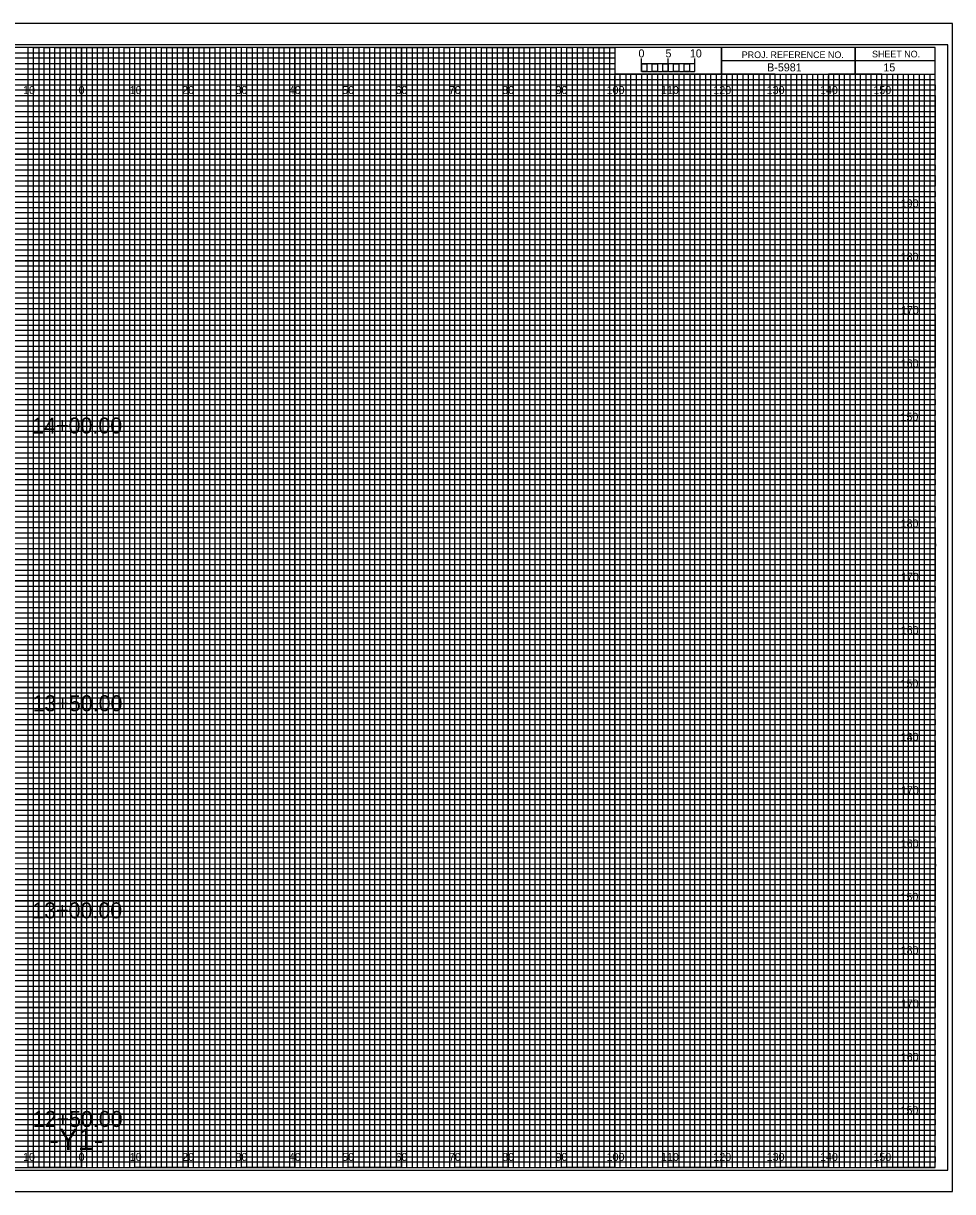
# Model space of a CAD drawing. Extents: x -13 to 323, y -5 to 434.
# Drawn here: x 149.1 to 323.3, y 215.5 to 434.5 of the extents above; entities that cross this region are included whole.
import ezdxf

# ---------------------------------------------------------------- set-up
doc = ezdxf.new("R2010")
doc.units = 0
for name, color, linetype in [('Exist Cross Section Cell', 7, 'Continuous'), ('Exist XS Center Line Elevation Label', 7, 'Continuous'), ('Exist XS Ground Line', 7, 'Continuous'), ('Prop CMT Concrete Structures', 7, 'Continuous'), ('Prop CMT Guardrail Graphics', 7, 'Continuous'), ('Prop CMT Pvmt Course 1', 7, 'Continuous'), ('Prop CMT Pvmt Course 2', 7, 'Continuous'), ('Prop CMT Pvmt Course 3', 7, 'Continuous'), ('Prop CMT Pvmt Surface', 7, 'Continuous'), ('Prop CMT Shld Paved Course 1', 7, 'Continuous'), ('Prop CMT Shld Paved Course 2', 7, 'Continuous'), ('Prop CMT Shld Paved Course 3', 7, 'Continuous'), ('Prop CMT Subgrade Earthwork', 7, 'Continuous'), ('Prop XS Ditch Standard Text', 7, 'Continuous'), ('Prop XS SE Text', 7, 'Continuous'), ('Prop XS Side Slope Text', 7, 'Continuous'), ('Scratch_Level_0', 7, 'Continuous')]:
    doc.layers.add(name, color=color, linetype=linetype)

msp = doc.modelspace()

# ---------------------------------------------------------------- linework, layer by layer
at = {"layer": 'Exist XS Center Line Elevation Label'}
for points in [[(145, 220), (155, 220), (155, 430), (165, 430), (165, 220), (175, 220), (175, 430), (185, 430), (185, 220), (195, 220), (195, 430), (205, 430), (205, 220), (215, 220), (215, 430), (225, 430), (225, 220), (235, 220), (235, 430), (245, 430), (245, 220), (255, 220), (255, 430), (259.93, 430), (260, 430), (260, 425), (264.99, 425), (264.99, 220), (275, 220), (275, 425), (285, 425), (285, 220), (295, 220), (295, 425), (305, 425), (305, 220), (315, 220), (315, 425)], [(0, 425), (275, 425)], [(0, 405), (320, 405), (320, 415), (0, 415)], [(0, 385), (320, 385), (320, 395), (0, 395)], [(0, 365), (320, 365), (320, 375), (0, 375)], [(0, 345), (320, 345), (320, 355), (0, 355)], [(0, 325), (320, 325), (320, 335), (0, 335)], [(0, 305), (320, 305), (320, 315), (0, 315)], [(0, 285), (320, 285), (320, 295), (0, 295)], [(0, 265), (320, 265), (320, 275), (0, 275)], [(0, 245), (320, 245), (320, 255), (0, 255)], [(0, 225), (320, 225), (320, 235), (0, 235)]]:
    msp.add_lwpolyline(points, dxfattribs=at)
at = {"layer": 'Exist XS Ground Line'}
for p, q in [((150, 430), (140, 430)), ((150, 220), (150, 430)), ((170, 430), (160, 430)), ((160, 430), (160, 220)), ((170, 220), (170, 430)), ((190, 430), (180, 430)), ((180, 430), (180, 220)), ((190, 220), (190, 430)), ((210, 430), (200, 430)), ((200, 430), (200, 220)), ((210, 220), (210, 430)), ((230, 430), (220, 430)), ((220, 430), (220, 220)), ((230, 220), (230, 430)), ((250, 430), (240, 430)), ((240, 430), (240, 220)), ((250, 220), (250, 430)), ((260, 430), (260, 220)), ((270, 220), (270, 425)), ((290, 425), (280, 425)), ((280, 425), (280, 220)), ((290, 220), (290, 425)), ((310, 425), (300, 425)), ((300, 425), (300, 220)), ((310, 220), (310, 425)), ((160, 220), (150, 220)), ((180, 220), (170, 220)), ((200, 220), (190, 220)), ((220, 220), (210, 220)), ((240, 220), (230, 220)), ((260, 220), (250, 220)), ((280, 220), (270, 220)), ((300, 220), (290, 220)), ((320, 220), (310, 220)), ((320, 220), (320, 220))]:
    msp.add_line(p, q, dxfattribs=at)
for points in [[(0, 420), (320, 420), (320, 410), (0, 410)], [(0, 400), (320, 400), (320, 390), (0, 390)], [(0, 380), (320, 380), (320, 370), (0, 370)], [(0, 360), (320, 360), (320, 350), (0, 350)], [(0, 340), (320, 340), (320, 330), (0, 330)], [(0, 320), (320, 320), (320, 310), (0, 310)], [(0, 300), (320, 300), (320, 290), (0, 290)], [(0, 280), (320, 280), (320, 270), (0, 270)], [(0, 260), (320, 260), (320, 250), (0, 250)], [(0, 240), (320, 240), (320, 230), (0, 230)]]:
    msp.add_lwpolyline(points, dxfattribs=at)
at = {"layer": 'Prop CMT Pvmt Course 1'}
for p, q in [((323.3, 434.5), (-13.4, 434.5)), ((-13.4, 215.5), (323.3, 215.5))]:
    msp.add_line(p, q, dxfattribs=at)
at = {"layer": 'Prop CMT Pvmt Course 2'}
msp.add_lwpolyline([(-13.4, 215.5), (323.3, 215.5), (323.3, 434.5), (-13.4, 434.5)], close=True, dxfattribs=at)
at = {"layer": 'Prop CMT Pvmt Course 3'}
msp.add_lwpolyline([(-10.8, 219.5), (322.4, 219.5), (322.4, 430.5), (-10.8, 430.5)], close=True, dxfattribs=at)
at = {"layer": 'Prop CMT Shld Paved Course 1'}
for p, q in [((305, 430), (305, 425)), ((305, 425), (305, 430)), ((280, 427.5), (280, 425)), ((320, 427.49), (280, 427.49)), ((280, 425), (320, 425))]:
    msp.add_line(p, q, dxfattribs=at)
for points in [[(320, 430), (0, 430), (0, 220), (320, 220)], [(280, 430), (260, 430), (260, 425.03), (280, 425.03)], [(320, 430), (280, 430), (280, 425), (320, 425)]]:
    msp.add_lwpolyline(points, close=True, dxfattribs=at)
at = {"layer": 'Prop CMT Shld Paved Course 2'}
for p, q in [((267, 425), (266.01, 425)), ((266.01, 425), (266.01, 220)), ((267, 220), (267, 425)), ((269, 425), (268, 425)), ((268, 425), (268, 220)), ((269, 220), (269, 425)), ((266.01, 220), (265, 220)), ((268, 220), (267, 220))]:
    msp.add_line(p, q, dxfattribs=at)
for points in [[(150, 220), (151, 220), (151, 430), (152, 430), (152, 220)], [(152, 220), (153, 220), (153, 430), (154, 430), (154, 220)], [(155, 220), (156, 220), (156, 430), (157, 430), (157, 220)], [(157, 220), (158, 220), (158, 430), (159, 430), (159, 220)], [(160, 220), (161, 220), (161, 430), (162, 430), (162, 220)], [(162, 220), (163, 220), (163, 430), (164, 430), (164, 220)], [(165, 220), (166, 220), (166, 430), (167, 430), (167, 220)], [(167, 220), (168, 220), (168, 430), (169, 430), (169, 220)], [(170, 220), (171, 220), (171, 430), (172, 430), (172, 220)], [(172, 220), (173, 220), (173, 430), (174, 430), (174, 220)], [(175, 220), (176, 220), (176, 430), (177, 430), (177, 220)], [(177, 220), (178, 220), (178, 430), (179, 430), (179, 220)], [(180, 220), (181, 220), (181, 430), (182, 430), (182, 220)], [(182, 220), (183, 220), (183, 430), (184, 430), (184, 220)], [(185, 220), (186, 220), (186, 430), (187, 430), (187, 220)], [(187, 220), (188, 220), (188, 430), (189, 430), (189, 220)], [(190, 220), (191, 220), (191, 430), (192, 430), (192, 220)], [(192, 220), (193, 220), (193, 430), (194, 430), (194, 220)], [(195, 220), (196, 220), (196, 430), (197, 430), (197, 220)], [(197, 220), (198, 220), (198, 430), (199, 430), (199, 220)], [(200, 220), (201, 220), (201, 430), (202, 430), (202, 220)], [(202, 220), (203, 220), (203, 430), (204, 430), (204, 220)], [(205, 220), (206, 220), (206, 430), (207, 430), (207, 220)], [(207, 220), (208, 220), (208, 430), (209, 430), (209, 220)], [(210, 220), (211, 220), (211, 430), (212, 430), (212, 220)], [(212, 220), (213, 220), (213, 430), (214, 430), (214, 220)], [(215, 220), (216, 220), (216, 430), (217, 430), (217, 220)], [(217, 220), (218, 220), (218, 430), (219, 430), (219, 220)], [(220, 220), (221, 220), (221, 430), (222, 430), (222, 220)], [(222, 220), (223, 220), (223, 430), (224, 430), (224, 220)], [(225, 220), (226, 220), (226, 430), (227, 430), (227, 220)], [(227, 220), (228, 220), (228, 430), (229, 430), (229, 220)], [(230, 220), (231, 220), (231, 430), (232, 430), (232, 220)], [(232, 220), (233, 220), (233, 430), (234, 430), (234, 220)], [(235, 220), (236, 220), (236, 430), (237, 430), (237, 220)], [(237, 220), (238, 220), (238, 430), (239, 430), (239, 220)], [(240, 220), (241, 220), (241, 430), (242, 430), (242, 220)], [(242, 220), (243, 220), (243, 430), (244, 430), (244, 220)], [(245, 220), (246, 220), (246, 430), (247, 430), (247, 220)], [(247, 220), (248, 220), (248, 430), (249, 430), (249, 220)], [(250, 220), (251, 220), (251, 430), (252, 430), (252, 220)], [(252, 220), (253, 220), (253, 430), (254, 430), (254, 220)], [(255, 220), (256, 220), (256, 430), (257, 430), (257, 220)], [(257, 220), (258, 220), (258, 430), (259, 430), (259, 220)], [(260, 220), (261, 220), (261, 425), (262.02, 425), (262.02, 220)], [(262, 220), (263, 220), (263, 425), (263.99, 425), (263.99, 220)], [(270, 220), (270.98, 220), (270.98, 425), (272, 425), (272, 220)], [(272, 220), (273, 220), (273, 425), (274.05, 425), (274.05, 220)], [(275, 220), (276, 220), (276, 425), (277, 425), (277, 220)], [(277, 220), (278, 220), (278, 425), (279, 425), (279, 220)], [(280, 220), (281, 220), (281, 425), (282, 425), (282, 220)], [(282, 220), (283, 220), (283, 425), (284, 425), (284, 220)], [(285, 220), (286, 220), (286, 425), (287, 425), (287, 220)], [(287, 220), (288, 220), (288, 425), (289, 425), (289, 220)], [(290, 220), (291, 220), (291, 425), (292, 425), (292, 220)], [(292, 220), (293, 220), (293, 425), (294, 425), (294, 220)], [(295, 220), (296, 220), (296, 425), (297, 425), (297, 220)], [(297, 220), (298, 220), (298, 425), (299, 425), (299, 220)], [(300, 220), (301, 220), (301, 425), (302, 425), (302, 220)], [(302, 220), (303, 220), (303, 425), (304, 425), (304, 220)], [(305, 220), (306, 220), (306, 425), (307, 425), (307, 220)], [(307, 220), (308, 220), (308, 425), (309, 425), (309, 220)], [(310, 220), (311, 220), (311, 425), (312, 425), (312, 220)], [(312, 220), (313, 220), (313, 425), (314, 425), (314, 220)], [(315, 220), (316, 220), (316, 425), (317, 425), (317, 220)], [(317, 220), (318, 220), (318, 425), (319, 425), (319, 220)]]:
    msp.add_lwpolyline(points, dxfattribs=at)
at = {"layer": 'Prop CMT Shld Paved Course 3'}
for p, q in [((265, 425.49), (265, 427.9)), ((265, 426.9), (265, 427.9)), ((270, 425.49), (270, 427.9)), ((275, 425.49), (275, 427.9)), ((275, 426.9), (275, 427.9))]:
    msp.add_line(p, q, dxfattribs=at)
for points in [[(275, 426.9), (265, 426.9), (265, 425.49), (275, 425.49)], [(265, 426.9), (266, 426.9), (266, 425.49), (265, 425.49)], [(267, 426.9), (268, 426.9), (268, 425.49), (267, 425.49)], [(269, 426.9), (270, 426.9), (270, 425.49), (269, 425.49)], [(271, 426.9), (272, 426.9), (272, 425.49), (271, 425.49)], [(273, 426.9), (274, 426.9), (274, 425.49), (273, 425.49)]]:
    msp.add_lwpolyline(points, close=True, dxfattribs=at)
at = {"layer": 'Prop CMT Subgrade Earthwork'}
for p, q in [((150, 220), (150, 430)), ((160, 220), (160, 430)), ((170, 220), (170, 430)), ((180, 220), (180, 430)), ((190, 220), (190, 430)), ((200, 220), (200, 430)), ((210, 220), (210, 430)), ((220, 220), (220, 430)), ((230, 220), (230, 430)), ((240, 220), (240, 430)), ((250, 220), (250, 430)), ((260, 220), (260, 424.69)), ((270, 220), (270, 424.69)), ((280, 220), (280, 424.69)), ((290, 220), (290, 424.69)), ((300, 220), (300, 424.69)), ((310, 220), (310, 424.69)), ((0, 420), (320, 420)), ((0, 410), (320, 410)), ((0, 400), (320, 400)), ((0, 390), (320, 390)), ((0, 380), (320, 380)), ((0, 370), (320, 370)), ((0, 360), (320, 360)), ((0, 350), (320, 350)), ((0, 340), (320, 340)), ((0, 330), (320, 330)), ((0, 320), (320, 320)), ((0, 310), (320, 310)), ((0, 300), (320, 300)), ((0, 290), (320, 290)), ((0, 280), (320, 280)), ((0, 270), (320, 270)), ((0, 260), (320, 260)), ((0, 250), (320, 250)), ((0, 240), (320, 240)), ((0, 230), (320, 230))]:
    msp.add_line(p, q, dxfattribs=at)
at = {"layer": 'Scratch_Level_0'}
for p, q in [((0, 429), (260, 429)), ((260, 427.98), (0, 427.98)), ((260, 429), (260, 427.98)), ((0, 427), (260, 427)), ((260, 425.89), (0, 425.89)), ((260, 427), (260, 425.89)), ((0, 424), (320, 424))]:
    msp.add_line(p, q, dxfattribs=at)
for points in [[(0, 423), (270, 423), (320, 423), (320, 422), (0, 422)], [(0, 421), (320, 421), (320, 419), (0, 419)], [(0, 418), (320, 418), (320, 417), (0, 416.98)], [(0, 416), (320, 416), (320, 414), (0, 414)], [(0, 413), (320, 413), (320, 412), (0, 412)], [(0, 411), (320, 411), (320, 409), (0, 409)], [(0, 408), (320, 408), (320, 407), (0, 407)], [(0, 406), (320, 406), (320, 404), (0, 404)], [(0, 403), (320, 403), (320, 402), (0, 402)], [(0, 401), (320, 401), (320, 399), (0, 399)], [(0, 398), (320, 398), (320, 397), (0, 397)], [(0, 396), (320, 396), (320, 393.95), (320, 393), (320, 392), (0, 392)], [(0, 394), (320, 394), (320, 393), (0, 393)], [(0, 391), (320, 391), (320, 389), (0, 389.03)], [(0, 389.03), (320, 389), (320, 388), (0, 388)], [(0, 387), (320, 387), (320, 386), (0, 386)], [(0, 384), (320, 384), (320, 383), (0, 383)], [(0, 382), (320, 382), (320, 381), (0, 381)], [(-0.07, 378.89), (320, 378.89), (320, 377.88), (-0.07, 377.88)], [(0, 377), (320, 377), (320, 376), (0, 376)], [(0, 374), (320, 374), (320, 373), (0, 373)], [(0, 372), (320, 372), (320, 371), (0, 371)], [(0, 369), (320, 369), (320, 368), (0, 368)], [(0, 367), (320, 367), (320, 366), (0, 366)], [(0, 364), (320, 364), (320, 363), (0, 363)], [(0, 362), (320, 362), (320, 361), (0, 361)], [(0, 359), (320, 359), (319.99, 357.98), (0, 358)], [(0, 357), (320, 357), (320, 356), (0, 356)], [(0, 354), (320, 354), (320, 353), (0, 353)], [(0, 352), (320, 352), (320, 351), (0, 351)], [(0, 349), (320, 349), (320, 348), (0, 348)], [(0, 347), (320, 347), (320, 346), (0, 346)], [(0, 344), (320, 344), (320, 343), (0, 343)], [(0, 342), (320, 342), (320, 341), (0, 341)], [(0, 339), (320, 339), (320, 338), (0, 338)], [(0, 336.99), (320.07, 336.91), (320, 336), (0, 336)], [(0, 334), (320, 334), (320, 333), (0, 333)], [(0, 332), (320, 332), (320, 331), (0, 331)], [(0, 329), (320, 329), (320, 328), (0, 328)], [(0, 327), (320, 327), (320, 326), (0, 326)], [(0, 324), (320, 324), (320, 323), (0, 323)], [(0, 322), (320, 322), (320, 321), (0, 321)], [(0, 319), (320, 319), (320, 318), (0, 318)], [(0, 317), (320, 317), (320, 316), (0, 316)], [(0, 314), (320, 314), (320, 313), (0, 313)], [(0, 312), (320, 312), (320, 311), (0, 311)], [(0, 309), (320, 309), (320, 308), (0, 308)], [(0, 307), (320, 307), (320, 306), (0, 306)], [(0, 304), (320, 304), (320, 303), (0, 303)], [(0, 302), (320, 302), (320, 301), (0, 301)], [(0, 299), (320, 299), (319.99, 297.98), (0, 298)], [(0, 297), (320, 297), (320, 296), (0, 296)], [(0, 294), (320, 294), (320, 293), (0, 293)], [(0, 292), (320, 292), (320, 291), (0, 291)], [(0, 289), (320, 289), (320, 288), (0, 288)], [(0, 287), (320, 287), (320, 286), (0, 286)], [(0, 284), (320, 284), (320, 283), (0, 283)], [(0, 282), (320, 282), (320, 281), (0, 281)], [(0, 279), (320, 279), (320, 278), (0, 278)], [(0, 276.99), (320.07, 276.91), (320, 276), (0, 276)], [(0, 274), (320, 274), (320, 273), (0, 273)], [(0, 272), (320, 272), (320, 271), (0, 271)], [(0, 269), (320, 269), (320, 268), (0, 268)], [(0, 267), (320, 267), (320, 266), (0, 266)], [(0, 264), (320, 264), (320, 263), (0, 263)], [(0, 262), (320, 262), (320, 261), (0, 261)], [(0, 259), (320, 259), (320, 258), (0, 258)], [(0, 257), (320, 257), (320, 256), (0, 256)], [(0, 254), (320, 254), (320, 253), (0, 253)], [(0, 252), (320, 252), (320, 251), (0, 251)], [(0, 249), (320, 249), (320, 248), (0, 248)], [(0, 247), (320, 247), (320, 246), (0, 246)], [(0, 244), (320, 244), (320, 243), (0, 243)], [(0, 242), (320, 242), (320, 241), (0, 241)], [(0, 239), (320, 239), (320, 238), (0, 238)], [(0, 237), (320, 237), (320, 236), (0, 236)], [(0, 234), (320, 234), (320, 233), (0, 233)], [(0, 232), (320, 232), (320, 231), (0, 231)], [(0, 229), (320, 229), (320, 228), (0, 228)], [(0, 227), (320, 227), (320, 226), (0, 226)], [(0, 224), (320, 224), (320, 223), (0, 223)], [(0, 222), (320, 222), (320, 221), (0, 221)]]:
    msp.add_lwpolyline(points, dxfattribs=at)

# ---------------------------------------------------------------- texts
at = {"layer": 'Exist Cross Section Cell'}
for s, p in [('10', (149.04, 421.25)), ('0', (159.45, 421.25)), ('0', (159.45, 421.25)), ('10', (169.04, 421.25)), ('20', (178.86, 421.25)), ('30', (188.86, 421.25)), ('40', (198.86, 421.25)), ('50', (208.86, 421.25)), ('60', (218.86, 421.25)), ('70', (228.86, 421.25)), ('80', (238.86, 421.25)), ('90', (248.86, 421.25)), ('100', (258.44, 421.25)), ('110', (268.62, 421.25)), ('120', (278.44, 421.25)), ('130', (288.44, 421.25)), ('140', (298.44, 421.25)), ('150', (308.44, 421.25)), ('10', (149.04, 221.25)), ('0', (159.45, 221.25)), ('0', (159.45, 221.25)), ('10', (169.04, 221.25)), ('20', (178.86, 221.25)), ('30', (188.86, 221.25)), ('40', (198.86, 221.25)), ('50', (208.86, 221.25)), ('60', (218.86, 221.25)), ('70', (228.86, 221.25)), ('80', (238.86, 221.25)), ('90', (248.86, 221.25)), ('100', (258.44, 221.25)), ('110', (268.62, 221.25)), ('120', (278.44, 221.25)), ('130', (288.44, 221.25)), ('140', (298.44, 221.25)), ('150', (308.44, 221.25))]:
    msp.add_text(s, height=1.5, dxfattribs=at).set_placement(p)
at = {"layer": 'Prop CMT Concrete Structures'}
for s, p in [('14+00.00', (150.77, 357.61)), ('13+50.00', (150.82, 305.55)), ('13+00.00', (150.77, 266.73)), ('12+50.00', (150.85, 227.62))]:
    msp.add_text(s, height=3, dxfattribs=at).set_placement(p)
at = {"layer": 'Prop CMT Guardrail Graphics'}
for s, p in [('190', (313.57, 400)), ('180', (313.55, 390)), ('170', (313.61, 380)), ('160', (313.57, 370)), ('150', (313.52, 360)), ('180', (313.55, 340)), ('170', (313.61, 330)), ('160', (313.57, 320)), ('150', (313.52, 310)), ('180', (313.55, 300)), ('140', (313.57, 300)), ('170', (313.61, 290)), ('160', (313.57, 280)), ('150', (313.52, 270)), ('180', (313.55, 260)), ('170', (313.61, 250)), ('160', (313.57, 240)), ('150', (313.52, 230))]:
    msp.add_text(s, height=1.5, dxfattribs=at).set_placement(p)
at = {"layer": 'Prop CMT Pvmt Surface'}
for s, p in [('5', (269.47, 428.12)), ('10', (274.04, 428.12))]:
    msp.add_text(s, height=1.5, dxfattribs=at).set_placement(p)
at = {"layer": 'Prop CMT Shld Paved Course 1'}
for s, p in [('PROJ. REFERENCE NO.', (283.77, 427.99)), ('SHEET NO.', (308.19, 428.12))]:
    msp.add_text(s, height=1.25, dxfattribs=at).set_placement(p)
at = {"layer": 'Prop CMT Shld Paved Course 3'}
msp.add_text('0', height=1.5, dxfattribs=at).set_placement((264.41, 428.12))
at = {"layer": 'Prop XS Ditch Standard Text'}
msp.add_text('-Y1-', height=4, dxfattribs=at).set_placement((153.97, 223.32))
at = {"layer": 'Prop XS SE Text'}
msp.add_text('B-5981', height=1.5, dxfattribs=at).set_placement((288.53, 425.5))
at = {"layer": 'Prop XS Side Slope Text'}
msp.add_text('15', height=1.5, dxfattribs=at).set_placement((310.32, 425.5))

doc.saveas('drawing.dxf')
